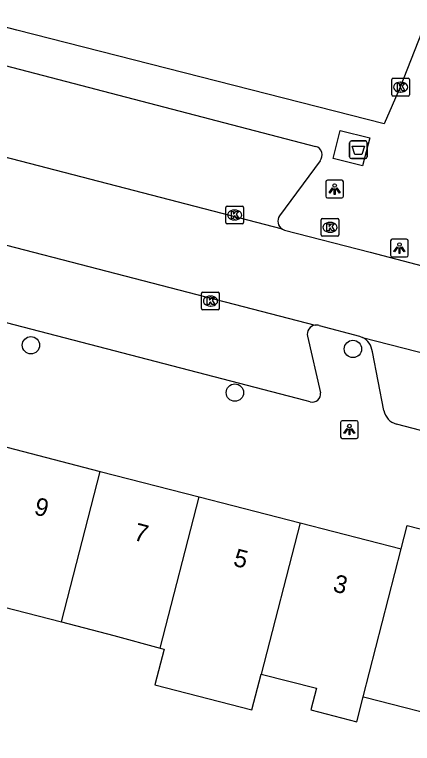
# Model space of a CAD drawing. Extents: x 163686 to 164493, y 382719 to 383870.
# Drawn here: x 164224.38 to 164246.8, y 383161.02 to 383202.14 of the extents above; entities that cross this region are included whole.
import ezdxf

# ---------------------------------------------------------------- set-up
doc = ezdxf.new("R2010")
doc.units = 0
for name, color, linetype in [('IMGEO_Afval_apart_plaats', 7, 'Continuous'), ('IMGEO_Boom', 7, 'Continuous'), ('IMGEO_Kolk', 7, 'Continuous'), ('IMGEO_Lichtpunt', 7, 'Continuous'), ('IMGEO_Pand', 7, 'Continuous'), ('IMGEO_Pand_nummerreeks', 7, 'Continuous'), ('IMGEO_Rijbaan_lokaal_open', 7, 'Continuous'), ('IMGEO_Voetpad_gesloten', 7, 'Continuous'), ('IMGEO_Voetpad_open', 7, 'Continuous')]:
    doc.layers.add(name, color=color, linetype=linetype)

msp = doc.modelspace()

# ---------------------------------------------------------------- linework, layer by layer
at = {"layer": 'IMGEO_Afval_apart_plaats'}
for p, q in [((164243.264, 383194.113), (164243.264, 383194.913)), ((164243.264, 383194.913), (164243.264, 383194.113)), ((164243.364, 383195.013), (164244.154, 383195.013)), ((164244.154, 383195.013), (164243.364, 383195.013)), ((164244.254, 383194.913), (164244.254, 383194.113)), ((164244.254, 383194.113), (164244.254, 383194.913)), ((164244.154, 383194.013), (164243.364, 383194.013)), ((164243.364, 383194.013), (164244.154, 383194.013))]:
    msp.add_line(p, q, dxfattribs=at)
msp.add_lwpolyline([(164243.407, 383194.727), (164244.111, 383194.727), (164243.962, 383194.257), (164243.556, 383194.257), (164243.407, 383194.727)], dxfattribs=at)
for centre, start, end in [((164243.364, 383194.913), 90, 180), ((164243.364, 383194.913), 90, 180), ((164244.154, 383194.913), 0, 90), ((164244.154, 383194.913), 360, 90), ((164243.364, 383194.113), 180, 270), ((164243.364, 383194.113), 180, 270), ((164244.154, 383194.113), 270, 0), ((164244.154, 383194.113), 270, 0)]:
    msp.add_arc(centre, 0.1, start, end, dxfattribs=at)
at = {"layer": 'IMGEO_Boom'}
for centre in [(164225.3, 383183.49), (164243.452, 383183.276), (164236.795, 383180.813)]:
    msp.add_circle(centre, 0.489, dxfattribs=at)
at = {"layer": 'IMGEO_Kolk'}
for p, q in [((164245.637, 383197.622), (164245.637, 383198.474)), ((164245.712, 383198.548), (164246.564, 383198.548)), ((164246.125, 383198.328), (164246.15, 383198.328)), ((164246.638, 383198.474), (164246.638, 383197.622)), ((164246.564, 383197.548), (164245.712, 383197.548)), ((164246.148, 383197.768), (164246.123, 383197.768)), ((164236.28, 383190.41), (164236.28, 383191.262)), ((164236.355, 383191.336), (164237.207, 383191.336)), ((164237.281, 383191.262), (164237.281, 383190.41)), ((164236.768, 383191.116), (164236.793, 383191.116)), ((164236.791, 383190.556), (164236.766, 383190.556)), ((164241.662, 383189.713), (164241.662, 383190.565)), ((164241.737, 383190.639), (164242.589, 383190.639)), ((164242.15, 383190.419), (164242.175, 383190.419)), ((164242.663, 383190.565), (164242.663, 383189.713)), ((164237.207, 383190.336), (164236.355, 383190.336)), ((164242.589, 383189.639), (164241.737, 383189.639)), ((164242.173, 383189.859), (164242.148, 383189.859)), ((164234.92, 383185.554), (164234.92, 383186.406)), ((164234.995, 383186.48), (164235.847, 383186.48)), ((164235.921, 383186.406), (164235.921, 383185.554)), ((164235.408, 383186.26), (164235.433, 383186.26)), ((164235.847, 383185.48), (164234.995, 383185.48)), ((164235.431, 383185.7), (164235.406, 383185.7))]:
    msp.add_line(p, q, dxfattribs=at)
for points in [[(164245.637, 383197.622), (164245.637, 383198.474)], [(164245.712, 383198.548), (164246.564, 383198.548)], [(164245.958, 383198.248), (164246.081, 383198.248), (164246.081, 383198.097), (164246.211, 383198.248), (164246.375, 383198.248), (164246.229, 383198.097), (164246.382, 383197.848), (164246.23, 383197.848), (164246.145, 383198.012), (164246.081, 383197.945), (164246.081, 383197.848), (164245.958, 383197.848), (164245.958, 383198.248)], [(164246.638, 383198.474), (164246.638, 383197.622)], [(164246.564, 383197.548), (164245.712, 383197.548)], [(164236.28, 383190.41), (164236.28, 383191.262)], [(164236.355, 383191.336), (164237.207, 383191.336)], [(164237.281, 383191.262), (164237.281, 383190.41)], [(164236.601, 383191.036), (164236.724, 383191.036), (164236.724, 383190.885), (164236.854, 383191.036), (164237.018, 383191.036), (164236.872, 383190.885), (164237.025, 383190.636), (164236.873, 383190.636), (164236.788, 383190.8), (164236.724, 383190.733), (164236.724, 383190.636), (164236.601, 383190.636), (164236.601, 383191.036)], [(164241.662, 383189.713), (164241.662, 383190.565)], [(164241.737, 383190.639), (164242.589, 383190.639)], [(164242.663, 383190.565), (164242.663, 383189.713)], [(164237.207, 383190.336), (164236.355, 383190.336)], [(164241.983, 383190.339), (164242.106, 383190.339), (164242.106, 383190.188), (164242.236, 383190.339), (164242.4, 383190.339), (164242.254, 383190.188), (164242.407, 383189.939), (164242.255, 383189.939), (164242.17, 383190.103), (164242.106, 383190.036), (164242.106, 383189.939), (164241.983, 383189.939), (164241.983, 383190.339)], [(164242.589, 383189.639), (164241.737, 383189.639)], [(164234.92, 383185.554), (164234.92, 383186.406)], [(164234.995, 383186.48), (164235.847, 383186.48)], [(164235.921, 383186.406), (164235.921, 383185.554)], [(164235.241, 383186.18), (164235.364, 383186.18), (164235.364, 383186.029), (164235.494, 383186.18), (164235.658, 383186.18), (164235.512, 383186.029), (164235.665, 383185.78), (164235.513, 383185.78), (164235.428, 383185.944), (164235.364, 383185.877), (164235.364, 383185.78), (164235.241, 383185.78), (164235.241, 383186.18)], [(164235.847, 383185.48), (164234.995, 383185.48)]]:
    msp.add_lwpolyline(points, dxfattribs=at)
for centre, start, end in [((164245.714, 383198.472), 91.552, 178.448), ((164245.714, 383198.472), 91.552, 178.448), ((164246.562, 383198.472), 1.552, 88.448), ((164246.562, 383198.472), 1.552, 88.448), ((164245.714, 383197.624), 181.552, 268.448), ((164245.714, 383197.624), 181.552, 268.448), ((164246.562, 383197.624), 271.552, 358.448), ((164246.562, 383197.624), 271.552, 358.448), ((164236.357, 383191.26), 91.552, 178.448), ((164236.357, 383191.26), 91.552, 178.448), ((164237.205, 383191.26), 1.552, 88.448), ((164237.205, 383191.26), 1.552, 88.448), ((164236.357, 383190.412), 181.552, 268.448), ((164236.357, 383190.412), 181.552, 268.448), ((164237.205, 383190.412), 271.552, 358.448), ((164237.205, 383190.412), 271.552, 358.448), ((164241.739, 383190.563), 91.552, 178.448), ((164241.739, 383190.563), 91.552, 178.448), ((164242.587, 383190.563), 1.552, 88.448), ((164242.587, 383190.563), 1.552, 88.448), ((164241.739, 383189.715), 181.552, 268.448), ((164241.739, 383189.715), 181.552, 268.448), ((164242.587, 383189.715), 271.552, 358.448), ((164242.587, 383189.715), 271.552, 358.448), ((164234.997, 383186.404), 91.552, 178.448), ((164234.997, 383186.404), 91.552, 178.448), ((164235.845, 383186.404), 1.552, 88.448), ((164235.845, 383186.404), 1.552, 88.448), ((164234.997, 383185.556), 181.552, 268.448), ((164234.997, 383185.556), 181.552, 268.448), ((164235.845, 383185.556), 271.552, 358.448), ((164235.845, 383185.556), 271.552, 358.448)]:
    msp.add_arc(centre, 0.0765, start, end, dxfattribs=at)
for centre, major_axis, ratio, start_param, end_param in [((164246.124, 383198.048), (-0.387, 0.002), 0.722429, 4.712389, 7.853982), ((164246.149, 383198.048), (-0.39, 0.002), 0.717154, 1.570796, 4.712389), ((164236.767, 383190.836), (-0.387, 0.002), 0.722429, 4.712389, 7.853982), ((164236.792, 383190.836), (-0.39, 0.002), 0.717154, 1.570796, 4.712389), ((164242.149, 383190.139), (-0.387, 0.002), 0.722429, 4.712389, 7.853982), ((164242.174, 383190.139), (-0.39, 0.002), 0.717154, 1.570796, 4.712389), ((164235.407, 383185.98), (-0.387, 0.002), 0.722429, 4.712389, 7.853982), ((164235.432, 383185.98), (-0.39, 0.002), 0.717154, 1.570796, 4.712389)]:
    msp.add_ellipse(centre, major_axis=major_axis, ratio=ratio, start_param=start_param, end_param=end_param, dxfattribs=at)
at = {"layer": 'IMGEO_Lichtpunt'}
for p, q in [((164241.921, 383192.698), (164241.921, 383191.891)), ((164241.921, 383192.698), (164241.921, 383191.891)), ((164242.823, 383192.793), (164242.015, 383192.793)), ((164242.823, 383192.793), (164242.015, 383192.793)), ((164242.917, 383191.891), (164242.917, 383192.698)), ((164242.917, 383191.891), (164242.917, 383192.698)), ((164242.015, 383191.797), (164242.823, 383191.797)), ((164242.015, 383191.797), (164242.823, 383191.797)), ((164245.575, 383189.375), (164245.575, 383188.568)), ((164245.575, 383189.375), (164245.575, 383188.568)), ((164246.477, 383189.47), (164245.669, 383189.47)), ((164246.477, 383189.47), (164245.669, 383189.47)), ((164246.571, 383188.568), (164246.571, 383189.375)), ((164246.571, 383188.568), (164246.571, 383189.375)), ((164245.669, 383188.474), (164246.477, 383188.474)), ((164245.669, 383188.474), (164246.477, 383188.474)), ((164242.755, 383179.13), (164242.755, 383178.323)), ((164242.755, 383179.13), (164242.755, 383178.323)), ((164243.657, 383179.225), (164242.849, 383179.225)), ((164243.657, 383179.225), (164242.849, 383179.225)), ((164243.751, 383178.323), (164243.751, 383179.13)), ((164243.751, 383178.323), (164243.751, 383179.13)), ((164242.849, 383178.229), (164243.657, 383178.229)), ((164242.849, 383178.229), (164243.657, 383178.229))]:
    msp.add_line(p, q, dxfattribs=at)
for points in [[(164242.295, 383192.362), (164242.334, 383192.334), (164242.146, 383192.072), (164242.108, 383192.099), (164242.295, 383192.362)], [(164242.397, 383192.314), (164242.444, 383192.314), (164242.444, 383191.992), (164242.397, 383191.992), (164242.397, 383192.314)], [(164242.507, 383192.334), (164242.545, 383192.361), (164242.732, 383192.099), (164242.693, 383192.071), (164242.507, 383192.334)], [(164245.949, 383189.039), (164245.988, 383189.011), (164245.8, 383188.749), (164245.762, 383188.776), (164245.949, 383189.039)], [(164246.051, 383188.991), (164246.098, 383188.991), (164246.098, 383188.669), (164246.051, 383188.669), (164246.051, 383188.991)], [(164246.161, 383189.011), (164246.199, 383189.038), (164246.386, 383188.776), (164246.347, 383188.748), (164246.161, 383189.011)], [(164243.129, 383178.794), (164243.168, 383178.766), (164242.98, 383178.504), (164242.942, 383178.531), (164243.129, 383178.794)], [(164243.231, 383178.746), (164243.278, 383178.746), (164243.278, 383178.424), (164243.231, 383178.424), (164243.231, 383178.746)], [(164243.341, 383178.766), (164243.379, 383178.793), (164243.566, 383178.531), (164243.527, 383178.503), (164243.341, 383178.766)]]:
    msp.add_lwpolyline(points, dxfattribs=at)
for centre in [(164242.42, 383192.496), (164246.074, 383189.173), (164243.254, 383178.928)]:
    msp.add_circle(centre, 0.0994, dxfattribs=at)
for centre, start, end in [((164242.015, 383192.698), 90, 180), ((164242.015, 383192.698), 90, 180), ((164242.823, 383192.698), 0, 90), ((164242.823, 383192.698), 0, 90), ((164242.015, 383191.891), 180, 270), ((164242.015, 383191.891), 180, 270), ((164242.823, 383191.891), 270, 0), ((164242.823, 383191.891), 270, 360), ((164245.669, 383189.375), 90, 180), ((164245.669, 383189.375), 90, 180), ((164246.477, 383189.375), 0, 90), ((164246.477, 383189.375), 0, 90), ((164245.669, 383188.568), 180, 270), ((164245.669, 383188.568), 180, 270), ((164246.477, 383188.568), 270, 0), ((164246.477, 383188.568), 270, 360), ((164242.849, 383179.13), 90, 180), ((164242.849, 383179.13), 90, 180), ((164243.657, 383179.13), 0, 90), ((164243.657, 383179.13), 0, 90), ((164242.849, 383178.323), 180, 270), ((164242.849, 383178.323), 180, 270), ((164243.657, 383178.323), 270, 0), ((164243.657, 383178.323), 270, 360)]:
    msp.add_arc(centre, 0.0946, start, end, dxfattribs=at)
at = {"layer": 'IMGEO_Pand'}
for points in [[(164223.493, 383177.845), (164229.208, 383176.371)], [(164227.019, 383167.88), (164229.208, 383176.371)], [(164229.208, 383176.371), (164234.784, 383174.933)], [(164232.586, 383166.405), (164234.784, 383174.933)], [(164234.784, 383174.933), (164240.47, 383173.467)], [(164240.47, 383173.467), (164238.271, 383164.937)], [(164240.47, 383173.467), (164246.163, 383171.999)], [(164246.163, 383171.999), (164246.501, 383173.309), (164253.068, 383171.616)], [(164244.031, 383163.658), (164246.163, 383171.999)], [(164221.304, 383169.354), (164224.387, 383168.559), (164227.019, 383167.88)], [(164227.019, 383167.88), (164229.966, 383167.12), (164232.586, 383166.405)], [(164232.586, 383166.405), (164232.81, 383166.345), (164232.281, 383164.325), (164237.75, 383162.914), (164238.271, 383164.937)], [(164238.271, 383164.937), (164241.392, 383164.132), (164241.077, 383162.91), (164243.669, 383162.241), (164244.031, 383163.658)], [(164244.031, 383163.658), (164244.128, 383163.633), (164249.406, 383162.272), (164254.247, 383161.023)]]:
    msp.add_lwpolyline(points, dxfattribs=at)
at = {"layer": 'IMGEO_Rijbaan_lokaal_open'}
for points in [[(164239.482, 383190.033), (164217.81, 383195.654)], [(164211.147, 383192.441), (164241.319, 383184.619)], [(164239.482, 383190.033), (164239.598, 383189.985), (164244.431, 383188.747), (164247.346, 383187.973), (164247.599, 383187.935)], [(164241.547, 383184.597), (164243.83, 383183.998), (164243.983, 383183.933)], [(164243.983, 383183.933), (164253.238, 383181.56)]]:
    msp.add_lwpolyline(points, dxfattribs=at)
msp.add_arc((164241.385, 383184.114), 0.51, 71.5013, 97.4757, dxfattribs=at)
at = {"layer": 'IMGEO_Voetpad_gesloten'}
msp.add_lwpolyline([(164242.735, 383195.611), (164244.403, 383195.185), (164243.999, 383193.601), (164242.331, 383194.027), (164242.735, 383195.611)], dxfattribs=at)
at = {"layer": 'IMGEO_Voetpad_open'}
for points in [[(164256.129, 383223.591), (164246.118, 383198.053), (164245.221, 383195.969), (164224.505, 383201.263), (164222.469, 383201.783), (164219.86, 383202.45)], [(164222.973, 383199.499), (164241.349, 383194.707)], [(164241.597, 383193.893), (164239.319, 383190.793)], [(164241.046, 383180.297), (164240.753, 383180.373), (164213.653, 383187.426)], [(164240.887, 383183.991), (164241.617, 383180.803)], [(164245.196, 383179.802), (164244.549, 383183.121)], [(164252.876, 383177.226), (164247.278, 383178.683), (164245.905, 383179.037)]]:
    msp.add_lwpolyline(points, dxfattribs=at)
for centre, radius, start, end in [((164241.213, 383194.221), 0.505, 319.5213, 74.3673), ((164239.736, 383190.485), 0.519, 143.568, 240.6421), ((164241.387, 383184.11), 0.514, 97.5955, 193.3565), ((164243.497, 383182.991), 1.06, 7.0483, 62.7081), ((164241.174, 383180.728), 0.45, 253.5036, 9.5888), ((164246.163, 383179.987), 0.985, 190.8494, 254.7992)]:
    msp.add_arc(centre, radius, start, end, dxfattribs=at)

# ---------------------------------------------------------------- texts
at = {"layer": 'IMGEO_Pand_nummerreeks'}
for s, p in [('9', (164225.427, 383173.959)), ('7', (164231.042, 383172.511)), ('5', (164236.657, 383171.063)), ('3', (164242.272, 383169.615))]:
    msp.add_text(s, height=1, rotation=345.5385, dxfattribs=at).set_placement(p)

doc.saveas('drawing.dxf')
